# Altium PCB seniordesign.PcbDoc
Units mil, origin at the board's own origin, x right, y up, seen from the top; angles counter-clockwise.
Board outline 1665 x 1745 mil, 2 copper layers (Top Layer, Bottom Layer); 10 components, 13 nets, 59 pads, 0 vias.
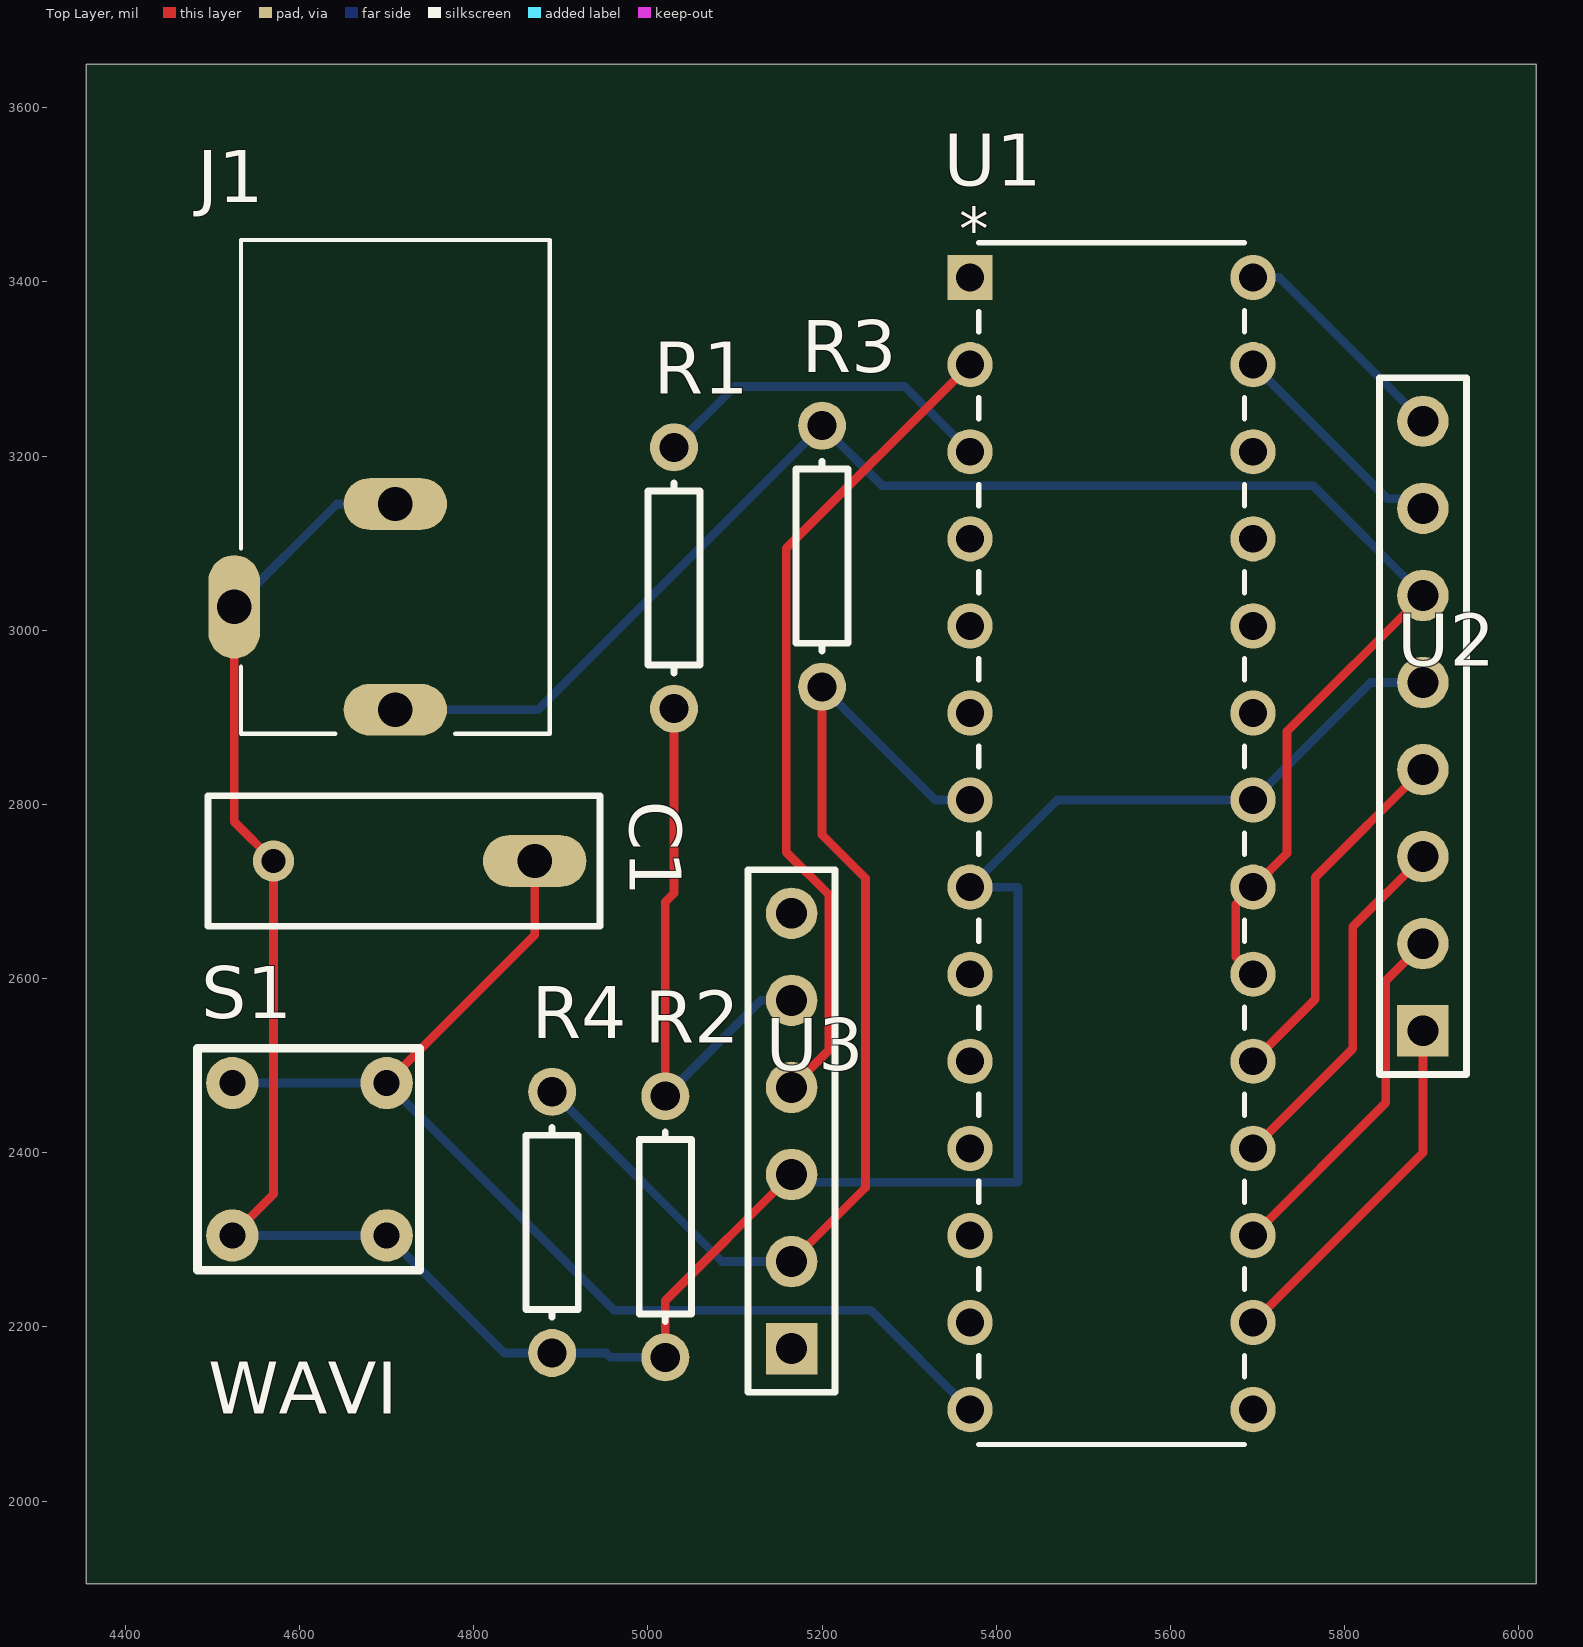
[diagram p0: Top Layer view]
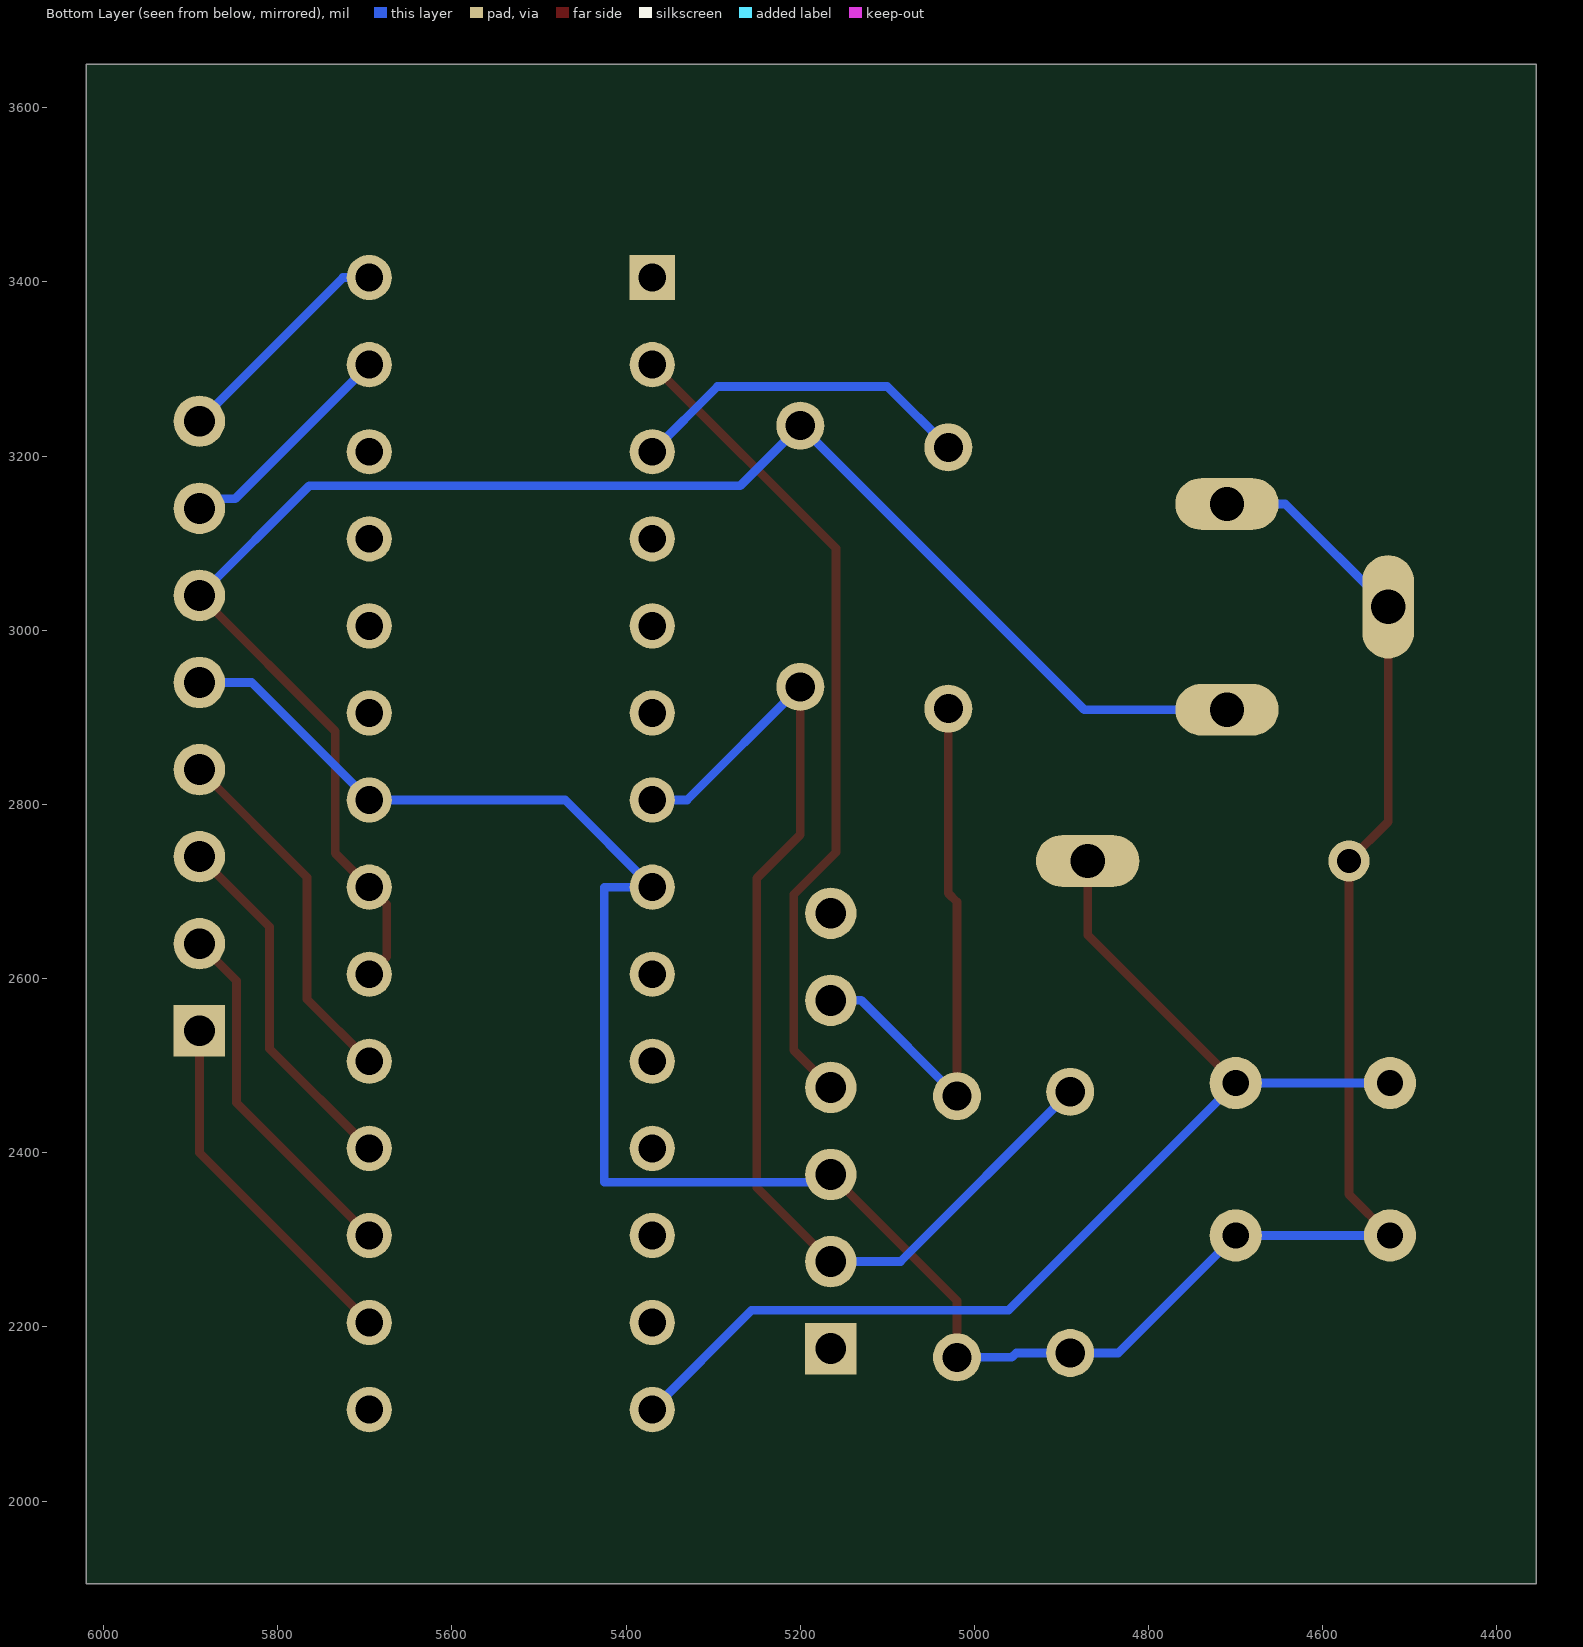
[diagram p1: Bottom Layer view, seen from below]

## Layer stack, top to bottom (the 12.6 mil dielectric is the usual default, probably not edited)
Top Solder: solder mask 0.4, Solder Resist, Dk 3.5
Top Layer: signal copper 1.4
Dielectric 1: dielectric 12.6, FR-4, Dk 4.8
Bottom Layer: signal copper 1.4
Bottom Solder: solder mask 0.4, Solder Resist, Dk 3.5

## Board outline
4355,1905 6020,1905 6020,3650 4355,3650

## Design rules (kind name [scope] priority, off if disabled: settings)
BoardOutlineClearance "BoardOutlineClearance Outside Layers" [OnLayer('Top Layer') or OnLayer('Bottom Layer')] p1: gap=10 ignorepadtopadclearanceinfootprint=FALSE except(0: Arc-SplitContinuation Track-SplitContinuation SMDPad-SplitContinuation THPad-SplitContinuation Via-SplitContinuation Fill-SplitContinuation Poly-SplitContinuation Region-SplitContinuation Text-SplitContinuation)
Clearance "Clearance Via to Trace" [IsVia vs IsTrack] p1: gap=12 ignorepadtopadclearanceinfootprint=FALSE
Clearance "Clearance Pad to Trace" [IsPad vs IsTrack] p2: gap=8 ignorepadtopadclearanceinfootprint=FALSE
Clearance "Clearance Different Net Vias" [IsVia vs IsVia] p3: gap=17 ignorepadtopadclearanceinfootprint=FALSE
Clearance "Clearance Same Net Vias" [IsVia vs IsVia] p4: gap=8 ignorepadtopadclearanceinfootprint=FALSE
Clearance "Clearance Same Net" [All] p5: gap=10 ignorepadtopadclearanceinfootprint=FALSE except(0: Arc-Hole Track-Hole SMDPad-Hole THPad-Hole Via-Hole Fill-Hole Poly-Hole Region-Hole Text-Hole; 8: Via-Via; 24.02: THPad-THPad)
Clearance "Clearance Different Net" [All] p6: gap=10 ignorepadtopadclearanceinfootprint=FALSE except(0: Arc-Hole Track-Hole SMDPad-Hole THPad-Hole Via-Hole Fill-Hole Poly-Hole Region-Hole Text-Hole; 17: Via-Via; 24.02: THPad-THPad)
HoleSize [All] p1: absolutevalues=TRUE maxlimit=255.91 minlimit=11.81 maxpercent=80.000 minpercent=20.000
PolygonConnect [All] p1: connectstyle=Relief reliefconductorwidth=10 reliefentries=4 polygonreliefangle="90 Angle" airgapwidth=10
RoomDefinition seniordesign [InComponentClass('seniordesign')] p1: confinementstyle=ConfineIn formatcopy=TRUE lockcomponents=FALSE outline 4375,1930 6010,1930 6010,3640 4375,3640
RoutingVias [All] p1: holewidth=28 width=50 viastyle="Through Hole" minholewidth=28 minwidth=50 maxholewidth=314.96 maxwidth=292.95
SilkToSilkClearance [All] p1: silktosilkclearance=8
SolderMaskExpansion [All] p1: expansion=4
UnRoutedNet [All] p1: checkbadconnections=TRUE
Width [All] p1: maxlimit=10 minlimit=6 preferedwidth=10
27 further rules are at their usual default settings.

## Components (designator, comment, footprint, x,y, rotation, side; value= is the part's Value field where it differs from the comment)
C1 "Cap" RAD-0.3 4720,2735 r0 top value=1uF
J1 "PJ-102A" *CUI_PJ-102A 4710,3026.89 r0 top
R1 "Res1" AXIAL-0.3 5030,3060 r90 top value=340
R2 "Res1" AXIAL-0.3 5020,2315 r90 top value=340
R3 "Res1" AXIAL-0.3 5200,3085 r90 top value=340
R4 "Res1" AXIAL-0.3 4890,2320 r90 top value=660
S1 "SW-PB" PCBComponent_1 4522.83,2480 r0 top
U1 "Part Number: ATMEGA328P-PN" 28P3 5695,2105 r0 top value=Value
U2 "Arducam" HDR1X8 5890,2540 r90 top
U3 "HC-05" HDR1X6 5165,2175 r90 top

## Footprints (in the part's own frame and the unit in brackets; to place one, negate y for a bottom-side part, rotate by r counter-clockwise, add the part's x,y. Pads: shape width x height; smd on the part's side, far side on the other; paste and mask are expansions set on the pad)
28P3 [mil]
  rect 52x52 hole 32 mask+0: 1(-325,1300)
  round 52 hole 32 mask+0: 2(-325,1200) 3(-325,1100) 4(-325,1000) 5(-325,900) 6(-325,800) 7(-325,700) 8(-325,600) 9(-325,500) 10(-325,400) 11(-325,300) 12(-325,200) 13(-325,100) 14(-325,0) 15(0,0) 16(0,100) 17(0,200) 18(0,300) 19(0,400) 20(0,500) 21(0,600) 22(0,700) 23(0,800) 24(0,900) 25(0,1000) 26(0,1100) 27(0,1200) 28(0,1300)
  silkscreen extent -315,-40 -10,1340, body extent 0,0 10,10, height 10
*CUI_PJ-102A [mm]
  oval 3.016x1.508 hole 1: 1(0,-3) 2(0,3)
  oval 1.508x3.016 hole 1: 3(-4.7,0)
  silkscreen extent -4.5,-3.7 4.5,10.7
AXIAL-0.3 [mm] "Axial Device, Thru-Hole; 2 Leads; 0.3 in Pin Spacing"
  round 1.4 hole 0.85: 1(-3.81,0) 2(3.81,0)
  silkscreen extent -2.77,-0.76 2.77,0.76
HDR1X6 [mm] "Connector; Header; 6 Position"
  rect 1.5x1.5 hole 0.9: 1(0,0)
  round 1.5 hole 0.9: 2(2.54,0) 3(5.08,0) 4(7.62,0) 5(10.16,0) 6(12.7,0)
  silkscreen extent -1.27,-1.27 13.97,1.27
HDR1X8 [mm] "Connector; Header; 8 Position"
  rect 1.5x1.5 hole 0.9: 1(0,0)
  round 1.5 hole 0.9: 2(2.54,0) 3(5.08,0) 4(7.62,0) 5(10.16,0) 6(12.7,0) 7(15.24,0) 8(17.78,0)
  silkscreen extent -1.27,-1.27 19.05,1.27
PCBComponent_1 [mil]
  round 60 hole 30: 1(0,0) 1(177.17,0) 2(0,-175) 2(177.17,-175)
  silkscreen extent -40,-215 215,40
RAD-0.3 [mm] "Radial Cap, Thru-Hole; 2 Leads; 0.3 in Pin Spacing"
  round 1.2 hole 0.7: 1(-3.81,0)
  oval 3.016x1.508 hole 1: 2(3.81,0)
  silkscreen extent -5.71,-1.91 5.71,1.91

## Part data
C1: "Capacitor"
R1 R2 R3 R4: "Resistor"
S1: "Switch"
U1: library part ATMEGA328P-PN, "No Description Available"
U3: "Bluetooth module"

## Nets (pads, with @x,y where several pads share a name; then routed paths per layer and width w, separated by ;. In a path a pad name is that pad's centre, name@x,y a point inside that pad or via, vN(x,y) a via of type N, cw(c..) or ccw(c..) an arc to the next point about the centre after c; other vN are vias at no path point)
GND: C1.1 J1.2 J1.3 R2.1 R4.1 S1.2 U1.8 U1.22 U2.5 U3.3 | length 3094.3
  Top Layer w10: S1.2@4522.83,2305 4570,2352.17 C1.1 4524.96,2780.04 J1.3 ; R2.1 5020,2230 U3.3
  Bottom Layer w10: S1.2@4522.83,2305 4700,2305 4835,2170 R4.1 4952,2170 4957,2165 R2.1 ; J1.3 4643.07,3145 J1.2 ; U3.3 5174,2366 5425,2366 5425,2705 U1.8 5470,2805 U1.22 5830,2940 U2.5
NetC1_2: C1.2 S1.1 U1.14 | length 1327.9
  Top Layer w10: S1.1@4700,2480 4870,2650 C1.2
  Bottom Layer w10: S1.1@4522.83,2480 4700,2480 4961,2219 5256,2219 U1.14
NetR1_1: R1.1 R2.2 U3.5 | length 639.7
  Top Layer w10: R2.2 5020,2688 5030,2698 R1.1
  Bottom Layer w10: R2.2 5130,2575 U3.5
NetR1_2: R1.2 U1.3 | length 400.1
  Bottom Layer w10: R1.2 5100,3280 5295,3280 U1.3
NetR3_1: R3.1 R4.2 U1.7 U3.2 | length 1295.5
  Top Layer w10: U3.2 5250,2360 5250,2715.06 5200,2765.06 R3.1
  Bottom Layer w10: R4.2 5085,2275 U3.2 ; R3.1 5330,2805 U1.7
NetU1_2: U1.2 U3.4 | length 955.1
  Top Layer w10: U3.4 5207.53,2517.53 5207.53,2696.47 5159,2745 5159,3094 U1.2
NetU1_16: U1.16 U2.1 | length 415.8
  Top Layer w10: U1.16 5890,2400 U2.1
NetU1_17: U1.17 U2.2 | length 415.8
  Top Layer w10: U1.17 5847.47,2457.47 5847.47,2597.47 U2.2
NetU1_18: U1.18 U2.3 | length 415.8
  Top Layer w10: U1.18 5809.43,2519.43 5809.43,2659.43 U2.3
NetU1_19: U1.19 U2.4 | length 415.8
  Top Layer w10: U1.19 5766.36,2576.36 5766.36,2716.36 U2.4
NetU1_27: U1.27 U2.7 | length 269.8
  Bottom Layer w10: U1.27 5849,3151 5890,3151 U2.7
NetU1_28: U1.28 U2.8 | length 263.3
  Bottom Layer w10: U1.28 5725,3405 U2.8
VCC: J1.1 R3.2 U1.20 U1.21 U2.6 | length 1928.2
  Top Layer w10: U1.20 5675,2625 5675,2685 U1.21 5734,2744 5734,2884 U2.6
  Bottom Layer w10: J1.1 4873.78,2908.78 R3.2 5269,3166 5764,3166 U2.6
pads on no net: U1.1 U1.4 U1.5 U1.6 U1.9 U1.10 U1.11 U1.12 U1.13 U1.15 U1.23 U1.24 U1.25 U1.26 U3.1 U3.6

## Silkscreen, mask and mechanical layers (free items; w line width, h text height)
Top Overlay:
  text "WAVI" at 4495,2100 h60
